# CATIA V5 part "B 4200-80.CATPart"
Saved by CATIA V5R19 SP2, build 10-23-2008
Part number: B 4200-80
Bounding box of the stored display mesh (mm): x -47.487 to 47.487, y -47.487 to 47.487, z 0 to 280
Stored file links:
  C:\Users\Bora\Desktop\3D Katı model\B serisi\B 4200\B 4200-80.CATPart
  C:\Program Files\Dassault Systemes\B19\intel_a\reffiles\standard\MetricThickPitch.txt
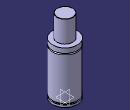
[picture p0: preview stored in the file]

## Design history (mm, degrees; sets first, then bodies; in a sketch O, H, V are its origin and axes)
Body1 (main body)
  Sketch1 on yz-plane, origin (0, 0, 0), H (0, 1, 0), V (0, 0, 1)
    point P1 (47.5, 178.5)
    point P2 (47.5, 173.5)
    point P3 (47.5, 178.5)
    point P6 (47.5, 173.5)
    point P9 (30, 279)
    point P11 (30, 279)
    arc A1 centre (47.5, 176) radius 2.5 from (47.5, 178.5) to (47.5, 173.5) ccw
    line L1 (47.5, 178.5) -> (47.5, 197)
    line L2 (47.5, 13) -> (47.5, 173.5)
    line L3 (43.5, 13) -> (43.5, 8)
    arc A2 centre (29, 279) radius 1 from (30, 279) to (29, 280) ccw
    line L4 (30, 279) -> (30, 197)
    line L5 (47.5, 0) -> (47.5, 8)
    line L6 (29, 280) -> (0, 280)
    point P15 (0, 280)
    line L7 (30, 197) -> (47.5, 197)
    line L8 (0, 0) -> (47.5, 0)
    line L9 (43.5, 13) -> (47.5, 13)
    line L10 (43.5, 8) -> (47.5, 8)
    coincidence: P15 V, P1 P3, P2 P6, P9 P11
    tangency: L6 A2
    horizontal: L7 H, L8 H, L9 H, L10 H
  Shaft1: profile Sketch1, axis Sketch1.V, angle 360
  Sketch2 on face of Shaft1 from Sketch1.L8, origin (0, 0, 0), H (1, 0, 0), V (0, -1, 0)
    point P1 (30, 0)
    distance P1 V = 30
  Hole1: placed by Sketch2, at (30, 0, 0) direction (0, 0, 1), diameter 6.647, depth 13, threaded "M8", thread diameter 8, thread depth 13, pitch 1.25
  CircPattern1: of Hole1, instances 4, angular step 90, axis from xy-plane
